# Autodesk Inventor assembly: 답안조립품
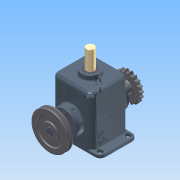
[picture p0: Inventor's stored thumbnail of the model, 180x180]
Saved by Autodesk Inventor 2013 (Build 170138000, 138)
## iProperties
Created: 2015-03
Part Number: 답안조립품
Document SubType Name: Assembly
Designer: Administrator
Mass: 8579.28 g
Surface Area: 4386.42 cm^2
Volume: 1982.54 cm^3
Density: 4.32742 g/cm^3
Author: Administrator
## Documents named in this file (15)
- C:\Documents and Settings\Administrator\바탕 화면\350305V1033\답안조립품.iam
- C:\Documents and Settings\Administrator\바탕 화면\350305V1033\본체.ipt
- C:\Documents and Settings\Administrator\바탕 화면\350305V1033\베어링 6205.ipt
- C:\Documents and Settings\Administrator\바탕 화면\350305V1033\편심축.ipt
- C:\Documents and Settings\Administrator\바탕 화면\350305V1033\오일실.ipt
- C:\Documents and Settings\Administrator\바탕 화면\350305V1033\커버.ipt
- C:\Documents and Settings\Administrator\바탕 화면\350305V1033\M4x0.5.ipt
- C:\Documents and Settings\Administrator\바탕 화면\350305V1033\체인 스프로킷.ipt
- C:\Documents and Settings\Administrator\바탕 화면\350305V1033\키 8x8.ipt
- C:\Documents and Settings\Administrator\바탕 화면\350305V1033\멈춤나사 M5x0.5.ipt
- C:\Documents and Settings\Administrator\바탕 화면\350305V1033\멈춤링.ipt
- C:\Documents and Settings\Administrator\바탕 화면\350305V1033\V-벨트풀리.ipt
- C:\Documents and Settings\Administrator\바탕 화면\350305V1033\부시.ipt
- C:\Documents and Settings\Administrator\바탕 화면\350305V1033\슬라이드.ipt
- C:\Documents and Settings\Administrator\바탕 화면\350305V1033\7-가변스프링.ipt
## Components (9 placed, 4 different names)
1. 5-체인 스프로킷:1 — 플러쉬:3, 각도:2
2. V-벨트풀리:1 — 플러쉬:4, 각도:4
3. 7-가변스프링:1
4. M4x0.5:1
5. M4x0.5:2
6. M4x0.5:3
7. M4x0.5:4
8. M4x0.5:5
9. M4x0.5:6
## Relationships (4: Flush 2, Angle 2)
- 플러쉬:3 [Flush]: 5-체인 스프로킷:1
- 각도:2 [Angle]: 5-체인 스프로킷:1
- 플러쉬:4 [Flush]: V-벨트풀리:1
- 각도:4 [Angle]: V-벨트풀리:1
